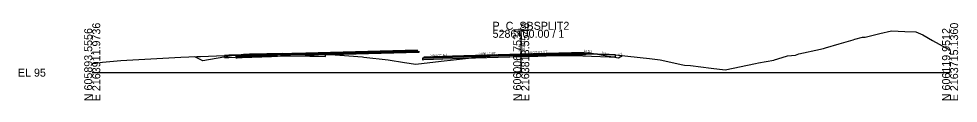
# Model space of a CAD drawing. Extents: x -26 to 1303, y -10 to 12033.
# Drawn here: x -25.7 to 302.8, y 3490.3 to 3517.8 of the extents above; entities that cross this region are included whole.
import ezdxf

# ---------------------------------------------------------------- set-up
doc = ezdxf.new("R2010")
doc.units = 0
for name, color, linetype in [('RD_GPK_XS_Cell', 7, 'Continuous'), ('RD_XS_Base', 7, 'Continuous'), ('RD_XS_ExGround', 7, 'Continuous'), ('RD_XS_ExPaveRet', 7, 'Continuous'), ('RD_XS_Greenside', 7, 'Continuous'), ('RD_XS_Pave', 7, 'Continuous'), ('RD_XS_PaveOvlay_CP', 7, 'Continuous'), ('RD_XS_TieSlope', 7, 'Continuous'), ('RD_XS_TX_Elev_EX', 7, 'Continuous'), ('RD_XS_TX_Elev_PR', 7, 'Continuous'), ('RD_XS_TX_ShdSlope', 7, 'Continuous'), ('RD_XS_TX_Slope', 7, 'Continuous')]:
    doc.layers.add(name, color=color, linetype=linetype)

msp = doc.modelspace()

# ---------------------------------------------------------------- linework, layer by layer
at = {"layer": 'RD_GPK_XS_Cell'}
for p, q in [((150, 3500), (150, 3515)), ((0, 3500), (150, 3500)), ((150, 3500), (300, 3500))]:
    msp.add_line(p, q, dxfattribs=at)
at = {"layer": 'RD_XS_Base'}
for p, q in [((50.25, 3505.67), (50.18, 3505.67)), ((50.18, 3505.67), (50.18, 3505.24)), ((50.68, 3505.69), (50.25, 3505.67)), ((52.42, 3505.76), (50.68, 3505.69)), ((62.68, 3506.17), (52.42, 3505.76)), ((52.42, 3505.26), (62.68, 3505.67)), ((64.78, 3506.22), (62.68, 3506.17)), ((62.68, 3505.67), (64.78, 3505.72)), ((74.68, 3506.48), (64.78, 3506.22)), ((64.78, 3505.72), (74.68, 3505.98)), ((74.68, 3506.48), (114.21, 3507.51)), ((114.21, 3507.01), (74.68, 3505.98)), ((74.68, 3505.98), (74.68, 3506.64)), ((74.68, 3506.64), (74.68, 3506.64)), ((74.68, 3506.64), (74.68, 3506.64)), ((74.68, 3506.64), (74.68, 3506.48)), ((74.68, 3506.48), (74.68, 3506.48)), ((74.68, 3505.98), (74.68, 3506.48)), ((74.68, 3506.48), (74.68, 3506.48)), ((74.68, 3506.48), (74.68, 3506.48)), ((74.68, 3505.98), (74.68, 3505.98)), ((98.68, 3507.1), (98.68, 3507.1)), ((98.68, 3507.1), (98.68, 3507.1)), ((98.68, 3506.6), (98.68, 3506.6)), ((98.68, 3506.6), (98.68, 3506.6)), ((113.71, 3507.49), (113.71, 3507.49)), ((114.21, 3507.51), (114.21, 3507.01)), ((114.21, 3507.47), (114.21, 3507.47)), ((126, 3505.45), (116, 3505.05)), ((150, 3506.12), (126, 3505.45)), ((126, 3504.95), (150, 3505.62)), ((126, 3505.45), (126, 3505.45)), ((150, 3506.12), (172, 3506.74)), ((150, 3505.62), (150, 3506.28)), ((150, 3506.28), (150, 3506.28)), ((150, 3506.28), (150, 3506.28)), ((150, 3506.28), (150, 3506.12)), ((172.5, 3506.25), (150, 3505.62)), ((150, 3506.12), (150, 3506.12)), ((150, 3505.62), (150, 3506.12)), ((150, 3506.12), (150, 3506.12)), ((150, 3506.12), (150, 3506.12)), ((150, 3505.62), (150, 3505.62)), ((162, 3506.46), (162, 3506.46)), ((162, 3506.46), (162, 3506.46)), ((162, 3505.96), (162, 3505.96)), ((162, 3505.96), (162, 3505.96)), ((172, 3506.74), (172, 3506.74)), ((172.5, 3506.75), (172.5, 3506.25)), ((172.5, 3506.72), (172.5, 3506.72)), ((50.18, 3505.24), (50.18, 3505.17)), ((50.18, 3505.17), (50.25, 3505.17)), ((50.25, 3505.17), (50.68, 3505.19)), ((50.68, 3505.19), (52.42, 3505.26)), ((116, 3505.05), (115.5, 3505.03)), ((115.5, 3505.03), (115.5, 3505.03)), ((115.5, 3505.03), (115.5, 3504.53)), ((115.5, 3504.53), (116, 3504.55)), ((116, 3505.05), (116, 3505.05)), ((116, 3504.55), (126, 3504.95)), ((116, 3504.55), (116, 3504.55)), ((126, 3504.95), (126, 3504.95))]:
    msp.add_line(p, q, dxfattribs=at)
at = {"layer": 'RD_XS_ExGround'}
msp.add_lwpolyline([(0, 3503.17), (1.23, 3503.37), (2.71, 3503.6), (3.55, 3503.69), (10.04, 3504.28), (30.95, 3505.36), (36.58, 3505.62), (37.01, 3505.66), (37.87, 3505.69), (46.25, 3506.03), (52.12, 3506.29), (54.97, 3506.41), (57.35, 3506.46), (59.05, 3506.5), (61.37, 3506.53), (64.27, 3506.57), (65.94, 3506.59), (66.59, 3506.65), (76.14, 3506.55), (81.6, 3506.45), (86.64, 3506.09), (94.52, 3505.5), (94.93, 3505.45), (103.44, 3504.5), (109.23, 3503.59), (113.15, 3502.94), (121.98, 3503.96), (126.38, 3504.5), (132.68, 3505.13), (136.15, 3505.5), (143.63, 3506.09), (145.49, 3506.23), (147.36, 3506.36), (153.6, 3506.5), (154.34, 3506.52), (155.52, 3506.55), (155.87, 3506.56), (161.68, 3506.75), (161.92, 3506.74), (163.12, 3506.72), (167.6, 3506.74), (167.63, 3506.74), (168.45, 3506.73), (180.82, 3506.33), (182.98, 3506.25), (194.92, 3504.91), (198.55, 3504.51), (206.49, 3502.77), (207.11, 3502.65), (209.21, 3502.5), (216.45, 3501.6), (221.29, 3500.99), (231.91, 3503.16), (232.97, 3503.38), (238.32, 3504.42), (238.54, 3504.47), (241.28, 3505.29), (243.17, 3505.83), (245.96, 3506.09), (247.08, 3506.57), (254.65, 3508.24), (255.62, 3508.43), (255.76, 3508.5), (256.38, 3508.68), (261.22, 3510.05), (266.07, 3511.48), (266.74, 3511.71), (269.34, 3512.42), (269.81, 3512.43), (270.35, 3512.43), (275.48, 3513.72), (279.53, 3514.6), (284.18, 3514.46), (288.07, 3514.31), (290.44, 3513.19), (293.9, 3511.22), (298.51, 3508.71), (300, 3508.01)], dxfattribs=at)
at = {"layer": 'RD_XS_ExPaveRet'}
for points in [[(81.6, 3506.45), (77.55, 3506.53), (76.14, 3506.55), (69.32, 3506.62), (66.59, 3506.65), (65.96, 3506.59), (65.94, 3506.59), (65.88, 3506.59), (64.27, 3506.57), (64.11, 3506.57), (61.37, 3506.53), (61.02, 3506.53), (59.05, 3506.5), (58.88, 3506.5), (57.35, 3506.46), (56.89, 3506.45), (54.97, 3506.41), (52.85, 3506.32), (52.12, 3506.29), (47.76, 3506.1), (46.25, 3506.03), (46.25, 3505.81), (46.25, 3505.28), (47.76, 3505.35), (52.12, 3505.54), (52.85, 3505.57), (54.97, 3505.66), (56.89, 3505.7), (57.35, 3505.71), (58.88, 3505.75), (59.05, 3505.75), (61.02, 3505.78), (61.37, 3505.78), (64.11, 3505.82), (64.27, 3505.82), (65.88, 3505.84), (65.94, 3505.84), (65.96, 3505.84), (66.59, 3505.9), (69.32, 3505.87), (76.14, 3505.8), (77.55, 3505.78), (81.6, 3505.7), (81.6, 3505.7), (81.6, 3505.7), (81.6, 3505.96), (81.6, 3506.45), (81.6, 3506.45), (81.6, 3506.45)], [(81.6, 3506.45), (77.55, 3506.53), (76.14, 3506.55), (69.32, 3506.62), (66.59, 3506.65), (65.96, 3506.59), (65.94, 3506.59), (65.88, 3506.59), (64.27, 3506.57), (64.11, 3506.57), (61.37, 3506.53), (61.02, 3506.53), (59.05, 3506.5), (58.88, 3506.5), (57.35, 3506.46), (56.89, 3506.45), (54.97, 3506.41), (52.85, 3506.32), (52.12, 3506.29), (47.76, 3506.1), (46.25, 3506.03), (46.25, 3505.81), (46.25, 3505.28), (47.76, 3505.35), (52.12, 3505.54), (52.85, 3505.57), (54.97, 3505.66), (56.89, 3505.7), (57.35, 3505.71), (58.88, 3505.75), (59.05, 3505.75), (61.02, 3505.78), (61.37, 3505.78), (64.11, 3505.82), (64.27, 3505.82), (65.88, 3505.84), (65.94, 3505.84), (65.96, 3505.84), (66.59, 3505.9), (69.32, 3505.87), (76.14, 3505.8), (77.55, 3505.78), (81.6, 3505.7), (81.6, 3505.7), (81.6, 3505.7), (81.6, 3505.96), (81.6, 3506.45), (81.6, 3506.45), (81.6, 3506.45)], [(180.82, 3506.33), (168.45, 3506.73), (168.45, 3506.73), (167.63, 3506.74), (167.6, 3506.74), (163.12, 3506.72), (163.12, 3506.72), (161.92, 3506.74), (161.92, 3506.74), (161.68, 3506.75), (161.68, 3506.75), (161.68, 3506.75), (155.87, 3506.56), (155.87, 3506.56), (155.52, 3506.55), (155.52, 3506.55), (154.34, 3506.52), (153.6, 3506.5), (153.6, 3506.5), (147.36, 3506.36), (147.36, 3506.36), (147.36, 3505.61), (153.6, 3505.75), (153.6, 3505.75), (154.34, 3505.77), (155.52, 3505.8), (155.52, 3505.8), (155.87, 3505.81), (155.87, 3505.81), (161.68, 3506), (161.68, 3506), (161.68, 3506), (161.92, 3505.99), (161.92, 3505.99), (163.12, 3505.97), (163.12, 3505.97), (167.6, 3505.99), (167.63, 3505.99), (168.45, 3505.98), (168.45, 3505.98), (180.82, 3505.58), (180.82, 3505.58), (182.98, 3505.5), (182.98, 3506.25), (182.98, 3506.25), (180.82, 3506.33), (180.82, 3506.33)], [(180.82, 3506.33), (168.45, 3506.73), (167.63, 3506.74), (167.6, 3506.74), (163.12, 3506.72), (161.92, 3506.74), (161.68, 3506.75), (155.87, 3506.56), (155.52, 3506.55), (154.34, 3506.52), (153.6, 3506.5), (147.36, 3506.36), (147.36, 3505.61), (153.6, 3505.75), (154.34, 3505.77), (155.52, 3505.8), (155.87, 3505.81), (161.68, 3506), (161.92, 3505.99), (163.12, 3505.97), (167.6, 3505.99), (167.63, 3505.99), (168.45, 3505.98), (180.82, 3505.58), (182.98, 3505.5), (182.98, 3506.25), (180.82, 3506.33)]]:
    msp.add_lwpolyline(points, dxfattribs=at)
at = {"layer": 'RD_XS_Greenside'}
for p, q in [((38.67, 3504.18), (35.86, 3505.59)), ((48.68, 3505.85), (38.67, 3504.18)), ((174, 3506.9), (184, 3505.23)), ((184, 3505.23), (185.48, 3505.97))]:
    msp.add_line(p, q, dxfattribs=at)
at = {"layer": 'RD_XS_Pave'}
for p, q in [((52.42, 3506.08), (50.68, 3506.01)), ((50.68, 3506.01), (50.68, 3505.87)), ((50.68, 3505.85), (52.42, 3505.92)), ((52.42, 3505.92), (50.68, 3505.85)), ((50.68, 3505.87), (50.68, 3505.85)), ((50.68, 3505.85), (50.68, 3505.71)), ((50.68, 3505.69), (52.42, 3505.76)), ((50.68, 3505.71), (50.68, 3505.69)), ((62.68, 3506.48), (52.42, 3506.08)), ((52.42, 3505.92), (62.68, 3506.33)), ((62.68, 3506.33), (52.42, 3505.92)), ((52.42, 3505.76), (62.68, 3506.17)), ((64.78, 3506.54), (62.68, 3506.48)), ((62.68, 3506.33), (64.78, 3506.38)), ((64.78, 3506.38), (62.68, 3506.33)), ((62.68, 3506.17), (64.78, 3506.22)), ((74.68, 3506.8), (64.78, 3506.54)), ((64.78, 3506.38), (74.68, 3506.64)), ((74.68, 3506.64), (64.78, 3506.38)), ((64.78, 3506.22), (74.68, 3506.48)), ((113.71, 3507.81), (74.68, 3506.8)), ((113.71, 3507.65), (74.68, 3506.64)), ((74.68, 3506.48), (113.71, 3507.49)), ((74.68, 3506.8), (74.68, 3506.8)), ((74.68, 3506.64), (74.68, 3506.64)), ((74.68, 3506.64), (74.68, 3506.64)), ((74.68, 3506.64), (74.68, 3506.48)), ((74.68, 3506.64), (74.68, 3506.64)), ((74.68, 3506.48), (74.68, 3506.64)), ((74.68, 3506.64), (74.68, 3506.64)), ((74.68, 3506.64), (74.68, 3506.64)), ((74.68, 3506.48), (74.68, 3506.48)), ((74.68, 3506.48), (74.68, 3506.48)), ((98.68, 3507.42), (98.68, 3507.42)), ((98.68, 3507.42), (98.68, 3507.42)), ((98.68, 3507.26), (98.68, 3507.26)), ((98.68, 3507.26), (98.68, 3507.26)), ((98.68, 3507.26), (98.68, 3507.26)), ((98.68, 3507.26), (98.68, 3507.26)), ((98.68, 3507.1), (98.68, 3507.1)), ((98.68, 3507.1), (98.68, 3507.1)), ((113.71, 3507.65), (113.71, 3507.81)), ((113.71, 3507.81), (113.71, 3507.81)), ((113.71, 3507.49), (113.71, 3507.65)), ((113.71, 3507.65), (113.71, 3507.65)), ((126, 3505.77), (116, 3505.37)), ((116, 3505.21), (126, 3505.61)), ((126, 3505.61), (116, 3505.21)), ((116, 3505.05), (126, 3505.45)), ((150, 3506.44), (126, 3505.77)), ((126, 3505.61), (150, 3506.28)), ((150, 3506.28), (126, 3505.61)), ((126, 3505.45), (150, 3506.12)), ((126, 3505.77), (126, 3505.77)), ((126, 3505.61), (126, 3505.61)), ((126, 3505.61), (126, 3505.61)), ((126, 3505.45), (126, 3505.45)), ((172, 3507.06), (150, 3506.44)), ((172, 3506.9), (150, 3506.28)), ((150, 3506.28), (172, 3506.9)), ((150, 3506.12), (172.5, 3506.75)), ((150, 3506.44), (150, 3506.44)), ((150, 3506.28), (150, 3506.28)), ((150, 3506.28), (150, 3506.28)), ((150, 3506.28), (150, 3506.12)), ((150, 3506.28), (150, 3506.28)), ((150, 3506.12), (150, 3506.28)), ((150, 3506.28), (150, 3506.28)), ((150, 3506.28), (150, 3506.28)), ((150, 3506.12), (150, 3506.12)), ((150, 3506.12), (150, 3506.12)), ((162, 3506.78), (162, 3506.78)), ((162, 3506.78), (162, 3506.78)), ((162, 3506.62), (162, 3506.62)), ((162, 3506.62), (162, 3506.62)), ((162, 3506.62), (162, 3506.62)), ((162, 3506.62), (162, 3506.62)), ((162, 3506.46), (162, 3506.46)), ((162, 3506.46), (162, 3506.46)), ((172, 3506.9), (172, 3507.06)), ((172, 3507.06), (172, 3507.06)), ((172, 3506.74), (172, 3506.9)), ((172, 3506.9), (172, 3506.9)), ((116, 3505.37), (116, 3505.37)), ((116, 3505.37), (116, 3505.21)), ((116, 3505.21), (116, 3505.21)), ((116, 3505.21), (116, 3505.05))]:
    msp.add_line(p, q, dxfattribs=at)
at = {"layer": 'RD_XS_PaveOvlay_CP'}
for p, q in [((52.42, 3506.08), (50.68, 3506.01)), ((62.68, 3506.48), (52.42, 3506.08)), ((64.78, 3506.54), (62.68, 3506.48)), ((74.68, 3506.8), (64.78, 3506.54)), ((113.71, 3507.81), (74.68, 3506.8)), ((74.68, 3506.8), (74.68, 3506.8)), ((98.68, 3507.42), (98.68, 3507.42)), ((98.68, 3507.42), (98.68, 3507.42)), ((126, 3505.77), (116, 3505.37)), ((150, 3506.44), (126, 3505.77)), ((126, 3505.77), (126, 3505.77)), ((172, 3507.06), (150, 3506.44)), ((150, 3506.44), (150, 3506.44)), ((162, 3506.78), (162, 3506.78)), ((162, 3506.78), (162, 3506.78))]:
    msp.add_line(p, q, dxfattribs=at)
at = {"layer": 'RD_XS_TieSlope'}
for p, q in [((50.68, 3506.01), (48.68, 3505.85)), ((172, 3507.06), (174, 3506.9))]:
    msp.add_line(p, q, dxfattribs=at)

# ---------------------------------------------------------------- texts
at = {"layer": 'RD_GPK_XS_Cell'}
for s, p in [('N 605893.5556', (0, 3490)), ('E 2163911.9736', (2.8, 3490)), ('N 606006.7534', (150, 3490)), ('E 2163813.5548', (152.8, 3490)), ('N 606119.9512', (300, 3490)), ('E 2163715.1360', (302.8, 3490))]:
    msp.add_text(s, height=2.8, rotation=90, dxfattribs=at).set_placement(p)
for s, p in [('P_C_SBSPLIT2', (140, 3515)), ('5286+00.00 / 1', (140, 3512.2)), ('EL 95', (-26, 3498.6))]:
    msp.add_text(s, height=2.8, dxfattribs=at).set_placement(p)
at = {"layer": 'RD_XS_TX_Elev_EX'}
msp.add_text('101.42', height=0.6, rotation=90, dxfattribs=at).set_placement((149.58, 3507.34))
at = {"layer": 'RD_XS_TX_Elev_PR'}
msp.add_text('101.44', height=1, rotation=90, dxfattribs=at).set_placement((151.33, 3507.08))
at = {"layer": 'RD_XS_TX_ShdSlope'}
msp.add_text('12.5:1', height=0.75, rotation=355.4261, dxfattribs=at).set_placement((171.84, 3507.29))
at = {"layer": 'RD_XS_TX_Slope'}
for s, rotation, p in [('0.040 FT./FT.', 2.2906, (118.15, 3505.6)), ('0.030 FT./FT.', 1.7184, (135.16, 3506.19)), ('0.030 FT./FT.', 1.7184, (153.16, 3506.73)), ('6:1', 350.5358, (178.13, 3506.61)), ('2:1', 26.5651, (184.21, 3505.77))]:
    msp.add_text(s, height=0.75, rotation=rotation, dxfattribs=at).set_placement(p)

doc.saveas('drawing.dxf')
